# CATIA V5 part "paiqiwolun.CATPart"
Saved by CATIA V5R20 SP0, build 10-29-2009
Part number: paiqiwolun
Material "无"
Bounding box of the stored display mesh (mm): x -38.539 to 38.539, y -38.539 to 38.539, z 0 to 46
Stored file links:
  C:\Users\Administrator\Desktop\paiqiwolun.CATPart
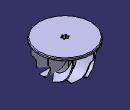
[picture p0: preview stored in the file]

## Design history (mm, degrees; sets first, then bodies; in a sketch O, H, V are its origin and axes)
Body1 (main body), material "无"
  DatumCurve1 to DatumCurve25
  Sketch1 on xy-plane, origin (0, 0, 0), H (1, 0, 0), V (0, 1, 0)
    projected arc E1 centre (0, 0) radius 3.5 from (0.6, -3.4482) to (2.6862, -2.2437) ccw from edge of DatumCurve1
    projected line E2 (3.7254, -2.8437) -> (2.6862, -2.2437) from edge of DatumCurve2
    projected line E3 (4.3254, -1.8045) -> (3.7254, -2.8437) from edge of DatumCurve3
    projected line E4 (3.2862, -1.2045) -> (4.3254, -1.8045) from edge of DatumCurve4
    projected arc E5 centre (0, 0) radius 3.5 from (3.2862, -1.2045) to (3.2862, 1.2045) ccw from edge of DatumCurve5
    projected line E6 (4.3254, 1.8045) -> (3.2862, 1.2045) from edge of DatumCurve6
    projected line E7 (3.7254, 2.8437) -> (4.3254, 1.8045) from edge of DatumCurve7
    projected line E8 (2.6862, 2.2437) -> (3.7254, 2.8437) from edge of DatumCurve8
    projected arc E9 centre (0, 0) radius 3.5 from (2.6862, 2.2437) to (0.6, 3.4482) ccw from edge of DatumCurve9
    projected line E10 (0.6, 4.6482) -> (0.6, 3.4482) from edge of DatumCurve10
    projected line E11 (-0.6, 4.6482) -> (0.6, 4.6482) from edge of DatumCurve11
    projected line E12 (-0.6, 3.4482) -> (-0.6, 4.6482) from edge of DatumCurve12
    projected arc E13 centre (0, 0) radius 3.5 from (-0.6, 3.4482) to (-2.6862, 2.2437) ccw from edge of DatumCurve13
    projected line E14 (-3.7254, 2.8437) -> (-2.6862, 2.2437) from edge of DatumCurve14
    projected line E15 (-4.3254, 1.8045) -> (-3.7254, 2.8437) from edge of DatumCurve15
    projected line E16 (-3.2862, 1.2045) -> (-4.3254, 1.8045) from edge of DatumCurve16
    projected arc E17 centre (0, 0) radius 3.5 from (-3.2862, 1.2045) to (-3.2862, -1.2045) ccw from edge of DatumCurve17
    projected line E18 (-4.3254, -1.8045) -> (-3.2862, -1.2045) from edge of DatumCurve18
    projected line E19 (-3.7254, -2.8437) -> (-4.3254, -1.8045) from edge of DatumCurve19
    projected line E20 (-2.6862, -2.2437) -> (-3.7254, -2.8437) from edge of DatumCurve20
    projected arc E21 centre (0, 0) radius 3.5 from (-2.6862, -2.2437) to (-0.6, -3.4482) ccw from edge of DatumCurve21
    projected line E22 (-0.6, -4.6482) -> (-0.6, -3.4482) from edge of DatumCurve22
    projected line E23 (0.6, -4.6482) -> (-0.6, -4.6482) from edge of DatumCurve23
    projected line E24 (0.6, -3.4482) -> (0.6, -4.6482) from edge of DatumCurve24
    projected circle E25 centre (0, 0) radius 12.5 from edge of DatumCurve25
  Pad1: profile Sketch1, direction (0, 0, 1), length 46
  DatumCurve26
  Sketch2 on end face of Pad1, origin (0, 0, 46), H (1, 0, 0), V (0, 1, 0)
    projected circle E1 centre (0, 0) radius 12.5 from edge of DatumCurve26
    circle A1 centre (0, 0) radius 38.5389
  Pad2: profile Sketch2, direction (0, 0, -1), length 4
  Sketch3 on yz-plane, origin (0, 0, 0), H (0, 1, 0), V (0, 0, 1)
    spline S1 through (11.9082, 42) (10.7846, 27.8473) (2.0458, 10.4941) (-10.8127, 5.9997)
    reference projected line E1 (-12.5, 42) -> (12.5, 42) from edge [face of Pad1 from Sketch1.E25 | end face of Pad2]
    offsetcurve C1
    construction line L1 (11.9082, 42) -> (10.6223, 41.9276)
    point P3 (11.9082, 42)
    construction line L2 through (11.9082, 42) direction (-0.0562, 0.9984)
    construction line L3 (-10.8127, 5.9997) -> (-10.8338, 7.2875)
    point P4 (-10.8127, 5.9997)
    construction line L4 through (-10.8127, 5.9997) direction (-0.9999, -0.0164)
    line L5 (11.9082, 42) -> (10.6223, 41.9276)
    point P5 (11.9082, 42)
    line L6 (-10.8127, 5.9997) -> (-10.8338, 7.2875)
    point P6 (-10.8127, 5.9997)
    point P7 (11.9082, 42)
    point P9 (-10.8127, 5.9997)
    coincidence: P7 E1, P7 P3, P9 P4, P7 P5, P9 P6
    tangency: L2 S1, L4 S1
    perpendicularity: L1 L2, L3 L4
  Pad3: profile Sketch3, direction (1, 0, 0), length 36
  Sketch4 on zx-plane, origin (0, 0, 0), H (0, 0, 1), V (1, 0, 0)
    spline S1 through (4.7327, 21.4538) (8.8118, 28.4269) (23.1241, 30.5041) (34.5514, 38.4353)
    line L1 (34.5514, 38.4353) -> (4.7327, 38.4353)
    line L2 (4.7327, 38.4353) -> (4.7327, 21.4538)
    point P2 (4.7327, 21.4538)
    point P3 (34.5514, 38.4353)
    point P4 (4.7327, 21.4538)
    point P5 (34.5514, 38.4353)
    horizontal: L1 H
    coincidence: P4 P2, P5 P3
    vertical: L2 V
  Pocket1: profile Sketch4, direction (0, -1, 0), length 20, mirrored extent
  CircPattern1: of Pad3, Pocket1, instances 10, angular step 40, axis from Z axis
  Fillet1: radius 1, on edge [face of Pad2 from Sketch2.A1 | face of Pad2]
  Fillet2: radius 1, on edge [end face of Pad2 | face of Pad2 from Sketch2.A1]
  Fillet3: radius 1, on edge [start face of Pad1 | face of Pad1 from Sketch1.E25]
